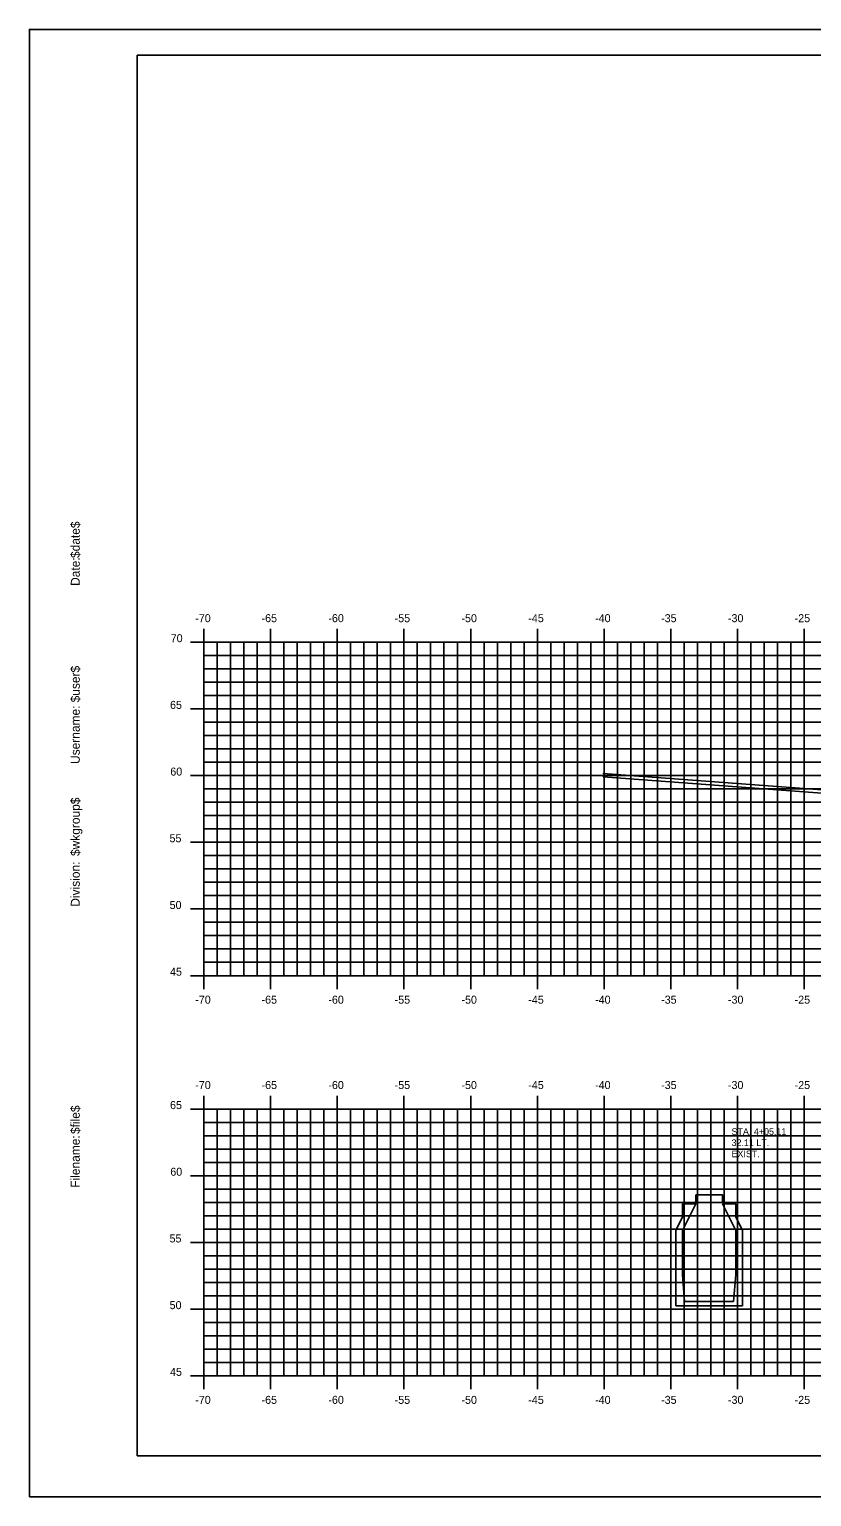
# Model space of a CAD drawing. Extents: x 1026213 to 1026383, y 394615 to 394725.
# Drawn here: x 1026213.3 to 1026272, y 394614.9 to 394724.9 of the extents above; entities that cross this region are included whole.
import ezdxf

# ---------------------------------------------------------------- set-up
doc = ezdxf.new("R2010")
doc.units = 0
for name, color, linetype in [('BORDER', 7, 'Continuous'), ('D_Text_Monospaced', 7, 'Continuous'), ('H_V ANNOTATION', 7, 'Continuous'), ('MAJOR', 7, 'Continuous'), ('MINOR', 7, 'Continuous'), ('PLOT BOUNDARY', 7, 'Continuous'), ('S_Drainage_CB', 7, 'Continuous'), ('S_Roadway_Centerline', 7, 'Continuous')]:
    doc.layers.add(name, color=color, linetype=linetype)

msp = doc.modelspace()

# ---------------------------------------------------------------- linework, layer by layer
at = {"layer": 'BORDER'}
for p, q in [((1026381.43, 394722.93), (1026221.43, 394722.93)), ((1026221.43, 394722.93), (1026221.43, 394617.93)), ((1026221.43, 394617.93), (1026381.43, 394617.93))]:
    msp.add_line(p, q, dxfattribs=at)
at = {"layer": 'MAJOR'}
for p, q in [((1026225.43, 394678.93), (1026226.43, 394678.93)), ((1026226.43, 394679.93), (1026226.43, 394678.93)), ((1026226.43, 394678.93), (1026366.43, 394678.93)), ((1026226.43, 394653.93), (1026226.43, 394678.93)), ((1026231.43, 394679.93), (1026231.43, 394678.93)), ((1026231.43, 394653.93), (1026231.43, 394678.93)), ((1026236.43, 394679.93), (1026236.43, 394678.93)), ((1026236.43, 394653.93), (1026236.43, 394678.93)), ((1026241.43, 394679.93), (1026241.43, 394678.93)), ((1026241.43, 394653.93), (1026241.43, 394678.93)), ((1026246.43, 394679.93), (1026246.43, 394678.93)), ((1026246.43, 394653.93), (1026246.43, 394678.93)), ((1026251.43, 394679.93), (1026251.43, 394678.93)), ((1026251.43, 394653.93), (1026251.43, 394678.93)), ((1026256.43, 394679.93), (1026256.43, 394678.93)), ((1026256.43, 394653.93), (1026256.43, 394678.93)), ((1026261.43, 394679.93), (1026261.43, 394678.93)), ((1026261.43, 394653.93), (1026261.43, 394678.93)), ((1026266.43, 394679.93), (1026266.43, 394678.93)), ((1026266.43, 394653.93), (1026266.43, 394678.93)), ((1026271.43, 394679.93), (1026271.43, 394678.93)), ((1026271.43, 394653.93), (1026271.43, 394678.93)), ((1026225.43, 394673.93), (1026226.43, 394673.93)), ((1026226.43, 394673.93), (1026366.43, 394673.93)), ((1026225.43, 394668.93), (1026226.43, 394668.93)), ((1026226.43, 394668.93), (1026366.43, 394668.93)), ((1026225.43, 394663.93), (1026226.43, 394663.93)), ((1026226.43, 394663.93), (1026366.43, 394663.93)), ((1026225.43, 394658.93), (1026226.43, 394658.93)), ((1026226.43, 394658.93), (1026366.43, 394658.93)), ((1026225.43, 394653.93), (1026226.43, 394653.93)), ((1026226.43, 394653.93), (1026366.43, 394653.93)), ((1026226.43, 394652.93), (1026226.43, 394653.93)), ((1026231.43, 394652.93), (1026231.43, 394653.93)), ((1026236.43, 394652.93), (1026236.43, 394653.93)), ((1026241.43, 394652.93), (1026241.43, 394653.93)), ((1026246.43, 394652.93), (1026246.43, 394653.93)), ((1026251.43, 394652.93), (1026251.43, 394653.93)), ((1026256.43, 394652.93), (1026256.43, 394653.93)), ((1026261.43, 394652.93), (1026261.43, 394653.93)), ((1026266.43, 394652.93), (1026266.43, 394653.93)), ((1026271.43, 394652.93), (1026271.43, 394653.93)), ((1026226.43, 394644.93), (1026226.43, 394643.93)), ((1026231.43, 394644.93), (1026231.43, 394643.93)), ((1026236.43, 394644.93), (1026236.43, 394643.93)), ((1026241.43, 394644.93), (1026241.43, 394643.93)), ((1026246.43, 394644.93), (1026246.43, 394643.93)), ((1026251.43, 394644.93), (1026251.43, 394643.93)), ((1026256.43, 394644.93), (1026256.43, 394643.93)), ((1026261.43, 394644.93), (1026261.43, 394643.93)), ((1026266.43, 394644.93), (1026266.43, 394643.93)), ((1026271.43, 394644.93), (1026271.43, 394643.93)), ((1026225.43, 394643.93), (1026226.43, 394643.93)), ((1026226.43, 394643.93), (1026366.43, 394643.93)), ((1026226.43, 394623.93), (1026226.43, 394643.93)), ((1026231.43, 394623.93), (1026231.43, 394643.93)), ((1026236.43, 394623.93), (1026236.43, 394643.93)), ((1026241.43, 394623.93), (1026241.43, 394643.93)), ((1026246.43, 394623.93), (1026246.43, 394643.93)), ((1026251.43, 394623.93), (1026251.43, 394643.93)), ((1026256.43, 394623.93), (1026256.43, 394643.93)), ((1026261.43, 394623.93), (1026261.43, 394643.93)), ((1026266.43, 394623.93), (1026266.43, 394643.93)), ((1026271.43, 394623.93), (1026271.43, 394643.93)), ((1026225.43, 394638.93), (1026226.43, 394638.93)), ((1026226.43, 394638.93), (1026366.43, 394638.93)), ((1026225.43, 394633.93), (1026226.43, 394633.93)), ((1026226.43, 394633.93), (1026366.43, 394633.93)), ((1026225.43, 394628.93), (1026226.43, 394628.93)), ((1026226.43, 394628.93), (1026366.43, 394628.93)), ((1026225.43, 394623.93), (1026226.43, 394623.93)), ((1026226.43, 394623.93), (1026366.43, 394623.93)), ((1026226.43, 394622.93), (1026226.43, 394623.93)), ((1026231.43, 394622.93), (1026231.43, 394623.93)), ((1026236.43, 394622.93), (1026236.43, 394623.93)), ((1026241.43, 394622.93), (1026241.43, 394623.93)), ((1026246.43, 394622.93), (1026246.43, 394623.93)), ((1026251.43, 394622.93), (1026251.43, 394623.93)), ((1026256.43, 394622.93), (1026256.43, 394623.93)), ((1026261.43, 394622.93), (1026261.43, 394623.93)), ((1026266.43, 394622.93), (1026266.43, 394623.93)), ((1026271.43, 394622.93), (1026271.43, 394623.93))]:
    msp.add_line(p, q, dxfattribs=at)
at = {"layer": 'MINOR'}
for p, q in [((1026227.43, 394653.93), (1026227.43, 394678.93)), ((1026228.43, 394653.93), (1026228.43, 394678.93)), ((1026229.43, 394653.93), (1026229.43, 394678.93)), ((1026230.43, 394653.93), (1026230.43, 394678.93)), ((1026232.43, 394653.93), (1026232.43, 394678.93)), ((1026233.43, 394653.93), (1026233.43, 394678.93)), ((1026234.43, 394653.93), (1026234.43, 394678.93)), ((1026235.43, 394653.93), (1026235.43, 394678.93)), ((1026237.43, 394653.93), (1026237.43, 394678.93)), ((1026238.43, 394653.93), (1026238.43, 394678.93)), ((1026239.43, 394653.93), (1026239.43, 394678.93)), ((1026240.43, 394653.93), (1026240.43, 394678.93)), ((1026242.43, 394653.93), (1026242.43, 394678.93)), ((1026243.43, 394653.93), (1026243.43, 394678.93)), ((1026244.43, 394653.93), (1026244.43, 394678.93)), ((1026245.43, 394653.93), (1026245.43, 394678.93)), ((1026247.43, 394653.93), (1026247.43, 394678.93)), ((1026248.43, 394653.93), (1026248.43, 394678.93)), ((1026249.43, 394653.93), (1026249.43, 394678.93)), ((1026250.43, 394653.93), (1026250.43, 394678.93)), ((1026252.43, 394653.93), (1026252.43, 394678.93)), ((1026253.43, 394653.93), (1026253.43, 394678.93)), ((1026254.43, 394653.93), (1026254.43, 394678.93)), ((1026255.43, 394653.93), (1026255.43, 394678.93)), ((1026257.43, 394653.93), (1026257.43, 394678.93)), ((1026258.43, 394653.93), (1026258.43, 394678.93)), ((1026259.43, 394653.93), (1026259.43, 394678.93)), ((1026260.43, 394653.93), (1026260.43, 394678.93)), ((1026262.43, 394653.93), (1026262.43, 394678.93)), ((1026263.43, 394653.93), (1026263.43, 394678.93)), ((1026264.43, 394653.93), (1026264.43, 394678.93)), ((1026265.43, 394653.93), (1026265.43, 394678.93)), ((1026267.43, 394653.93), (1026267.43, 394678.93)), ((1026268.43, 394653.93), (1026268.43, 394678.93)), ((1026269.43, 394653.93), (1026269.43, 394678.93)), ((1026270.43, 394653.93), (1026270.43, 394678.93)), ((1026226.43, 394677.93), (1026366.43, 394677.93)), ((1026226.43, 394677.93), (1026227.44, 394677.93)), ((1026226.43, 394676.93), (1026366.43, 394676.93)), ((1026226.43, 394676.93), (1026227.44, 394676.93)), ((1026226.43, 394675.93), (1026366.43, 394675.93)), ((1026226.43, 394675.93), (1026227.44, 394675.93)), ((1026226.43, 394674.93), (1026366.43, 394674.93)), ((1026226.43, 394674.93), (1026227.44, 394674.93)), ((1026226.43, 394672.93), (1026366.43, 394672.93)), ((1026226.43, 394672.93), (1026227.44, 394672.93)), ((1026226.43, 394671.93), (1026366.43, 394671.93)), ((1026226.43, 394671.93), (1026227.44, 394671.93)), ((1026226.43, 394670.93), (1026366.43, 394670.93)), ((1026226.43, 394670.93), (1026227.44, 394670.93)), ((1026226.43, 394669.93), (1026366.43, 394669.93)), ((1026226.43, 394669.93), (1026227.44, 394669.93)), ((1026226.43, 394667.93), (1026366.43, 394667.93)), ((1026226.43, 394667.93), (1026227.44, 394667.93)), ((1026226.43, 394666.93), (1026366.43, 394666.93)), ((1026226.43, 394666.93), (1026227.44, 394666.93)), ((1026226.43, 394665.93), (1026366.43, 394665.93)), ((1026226.43, 394665.93), (1026227.44, 394665.93)), ((1026226.43, 394664.93), (1026366.43, 394664.93)), ((1026226.43, 394664.93), (1026227.44, 394664.93)), ((1026226.43, 394662.93), (1026366.43, 394662.93)), ((1026226.43, 394662.93), (1026227.44, 394662.93)), ((1026226.43, 394661.93), (1026366.43, 394661.93)), ((1026226.43, 394661.93), (1026227.44, 394661.93)), ((1026226.43, 394660.93), (1026366.43, 394660.93)), ((1026226.43, 394660.93), (1026227.44, 394660.93)), ((1026226.43, 394659.93), (1026366.43, 394659.93)), ((1026226.43, 394659.93), (1026227.44, 394659.93)), ((1026226.43, 394657.93), (1026366.43, 394657.93)), ((1026226.43, 394657.93), (1026227.44, 394657.93)), ((1026226.43, 394656.93), (1026366.43, 394656.93)), ((1026226.43, 394656.93), (1026227.44, 394656.93)), ((1026226.43, 394655.93), (1026366.43, 394655.93)), ((1026226.43, 394655.93), (1026227.44, 394655.93)), ((1026226.43, 394654.93), (1026366.43, 394654.93)), ((1026226.43, 394654.93), (1026227.44, 394654.93)), ((1026227.43, 394623.93), (1026227.43, 394643.93)), ((1026228.43, 394623.93), (1026228.43, 394643.93)), ((1026229.43, 394623.93), (1026229.43, 394643.93)), ((1026230.43, 394623.93), (1026230.43, 394643.93)), ((1026232.43, 394623.93), (1026232.43, 394643.93)), ((1026233.43, 394623.93), (1026233.43, 394643.93)), ((1026234.43, 394623.93), (1026234.43, 394643.93)), ((1026235.43, 394623.93), (1026235.43, 394643.93)), ((1026237.43, 394623.93), (1026237.43, 394643.93)), ((1026238.43, 394623.93), (1026238.43, 394643.93)), ((1026239.43, 394623.93), (1026239.43, 394643.93)), ((1026240.43, 394623.93), (1026240.43, 394643.93)), ((1026242.43, 394623.93), (1026242.43, 394643.93)), ((1026243.43, 394623.93), (1026243.43, 394643.93)), ((1026244.43, 394623.93), (1026244.43, 394643.93)), ((1026245.43, 394623.93), (1026245.43, 394643.93)), ((1026247.43, 394623.93), (1026247.43, 394643.93)), ((1026248.43, 394623.93), (1026248.43, 394643.93)), ((1026249.43, 394623.93), (1026249.43, 394643.93)), ((1026250.43, 394623.93), (1026250.43, 394643.93)), ((1026252.43, 394623.93), (1026252.43, 394643.93)), ((1026253.43, 394623.93), (1026253.43, 394643.93)), ((1026254.43, 394623.93), (1026254.43, 394643.93)), ((1026255.43, 394623.93), (1026255.43, 394643.93)), ((1026257.43, 394623.93), (1026257.43, 394643.93)), ((1026258.43, 394623.93), (1026258.43, 394643.93)), ((1026259.43, 394623.93), (1026259.43, 394643.93)), ((1026260.43, 394623.93), (1026260.43, 394643.93)), ((1026262.43, 394623.93), (1026262.43, 394643.93)), ((1026263.43, 394623.93), (1026263.43, 394643.93)), ((1026264.43, 394623.93), (1026264.43, 394643.93)), ((1026265.43, 394623.93), (1026265.43, 394643.93)), ((1026267.43, 394623.93), (1026267.43, 394643.93)), ((1026268.43, 394623.93), (1026268.43, 394643.93)), ((1026269.43, 394623.93), (1026269.43, 394643.93)), ((1026270.43, 394623.93), (1026270.43, 394643.93)), ((1026226.43, 394642.93), (1026366.43, 394642.93)), ((1026226.43, 394642.93), (1026227.44, 394642.93)), ((1026226.43, 394641.93), (1026366.43, 394641.93)), ((1026226.43, 394641.93), (1026227.44, 394641.93)), ((1026226.43, 394640.93), (1026366.43, 394640.93)), ((1026226.43, 394640.93), (1026227.44, 394640.93)), ((1026226.43, 394639.93), (1026366.43, 394639.93)), ((1026226.43, 394639.93), (1026227.44, 394639.93)), ((1026226.43, 394637.93), (1026366.43, 394637.93)), ((1026226.43, 394637.93), (1026227.44, 394637.93)), ((1026226.43, 394636.93), (1026366.43, 394636.93)), ((1026226.43, 394636.93), (1026227.44, 394636.93)), ((1026226.43, 394635.93), (1026366.43, 394635.93)), ((1026226.43, 394635.93), (1026227.44, 394635.93)), ((1026226.43, 394634.93), (1026366.43, 394634.93)), ((1026226.43, 394634.93), (1026227.44, 394634.93)), ((1026226.43, 394632.93), (1026366.43, 394632.93)), ((1026226.43, 394632.93), (1026227.44, 394632.93)), ((1026226.43, 394631.93), (1026366.43, 394631.93)), ((1026226.43, 394631.93), (1026227.44, 394631.93)), ((1026226.43, 394630.93), (1026366.43, 394630.93)), ((1026226.43, 394630.93), (1026227.44, 394630.93)), ((1026226.43, 394629.93), (1026366.43, 394629.93)), ((1026226.43, 394629.93), (1026227.44, 394629.93)), ((1026226.43, 394627.93), (1026366.43, 394627.93)), ((1026226.43, 394627.93), (1026227.44, 394627.93)), ((1026226.43, 394626.93), (1026366.43, 394626.93)), ((1026226.43, 394626.93), (1026227.44, 394626.93)), ((1026226.43, 394625.93), (1026366.43, 394625.93)), ((1026226.43, 394625.93), (1026227.44, 394625.93)), ((1026226.43, 394624.93), (1026366.43, 394624.93)), ((1026226.43, 394624.93), (1026227.44, 394624.93))]:
    msp.add_line(p, q, dxfattribs=at)
at = {"layer": 'PLOT BOUNDARY'}
msp.add_lwpolyline([(1026213.34, 394614.87), (1026383.34, 394614.87), (1026383.34, 394724.87), (1026213.34, 394724.87)], close=True, dxfattribs=at)
at = {"layer": 'S_Drainage_CB'}
for p, q in [((1026262.31, 394635.84), (1026262.31, 394636.83)), ((1026262.31, 394636.83), (1026263.32, 394636.83)), ((1026263.32, 394636.83), (1026262.31, 394634.83)), ((1026262.31, 394635.84), (1026262.31, 394636.83)), ((1026262.31, 394636.83), (1026263.32, 394636.83)), ((1026263.32, 394636.83), (1026262.31, 394634.83)), ((1026265.32, 394636.83), (1026266.31, 394636.83)), ((1026266.31, 394634.83), (1026265.32, 394636.83)), ((1026265.32, 394636.83), (1026266.31, 394636.83)), ((1026266.31, 394634.83), (1026265.32, 394636.83)), ((1026266.31, 394636.83), (1026266.31, 394635.84)), ((1026266.31, 394636.83), (1026266.31, 394635.84)), ((1026261.81, 394634.83), (1026262.31, 394635.84)), ((1026261.81, 394634.83), (1026262.31, 394635.84)), ((1026266.31, 394635.84), (1026266.8, 394634.83)), ((1026266.31, 394635.84), (1026266.8, 394634.83)), ((1026261.81, 394629.18), (1026261.81, 394634.83)), ((1026261.81, 394629.18), (1026261.81, 394634.83)), ((1026262.31, 394634.83), (1026262.31, 394631.51)), ((1026262.31, 394634.83), (1026262.31, 394631.51)), ((1026266.31, 394631.51), (1026266.31, 394634.83)), ((1026266.31, 394631.51), (1026266.31, 394634.83)), ((1026266.8, 394634.83), (1026266.8, 394629.18)), ((1026266.8, 394634.83), (1026266.8, 394629.18)), ((1026262.31, 394631.51), (1026262.47, 394629.51)), ((1026262.31, 394631.51), (1026262.47, 394629.51)), ((1026266.14, 394629.51), (1026266.31, 394631.51)), ((1026266.14, 394629.51), (1026266.31, 394631.51)), ((1026262.47, 394629.51), (1026266.14, 394629.51)), ((1026262.47, 394629.51), (1026266.14, 394629.51)), ((1026266.8, 394629.18), (1026261.81, 394629.18)), ((1026266.8, 394629.18), (1026261.81, 394629.18))]:
    msp.add_line(p, q, dxfattribs=at)
msp.add_lwpolyline([(1026262.83, 394636.87), (1026263.32, 394636.87), (1026263.32, 394637.49), (1026265.32, 394637.49), (1026265.32, 394636.87), (1026265.82, 394636.87)], dxfattribs=at)
msp.add_lwpolyline([(1026262.83, 394636.87), (1026263.32, 394636.87), (1026263.32, 394637.49), (1026265.32, 394637.49), (1026265.32, 394636.87), (1026265.82, 394636.87)], dxfattribs=at)
at = {"layer": 'S_Roadway_Centerline'}
for points in [[(1026256.36, 394669.08), (1026256.36, 394669.08), (1026258.36, 394668.94), (1026278.77, 394667.41), (1026280.04, 394667.3), (1026280.16, 394667.29), (1026299.85, 394666.05), (1026302.39, 394665.94), (1026303.98, 394665.86), (1026303.98, 394665.86), (1026303.98, 394665.86), (1026309.14, 394665.64), (1026309.14, 394665.64), (1026312.05, 394665.32), (1026323.69, 394664.41), (1026333.54, 394663.54), (1026333.54, 394663.54), (1026333.55, 394663.54), (1026346.49, 394662.46), (1026346.49, 394662.46), (1026363.44, 394661.04), (1026365.47, 394660.9), (1026365.47, 394660.9), (1026366.43, 394660.82)], [(1026256.36, 394668.83), (1026256.36, 394668.83), (1026258.36, 394668.69), (1026278.77, 394667.16), (1026280.04, 394667.05), (1026280.16, 394667.04), (1026299.85, 394665.8), (1026302.39, 394665.69), (1026303.98, 394665.61), (1026303.98, 394665.61), (1026303.98, 394665.61), (1026309.14, 394665.39), (1026309.14, 394665.39), (1026312.05, 394665.07), (1026323.69, 394664.16), (1026333.54, 394663.29), (1026333.54, 394663.29), (1026333.55, 394663.29), (1026346.49, 394662.21), (1026346.49, 394662.21), (1026363.44, 394660.79), (1026365.47, 394660.65), (1026365.47, 394660.65), (1026366.43, 394660.57)]]:
    msp.add_lwpolyline(points, dxfattribs=at)

# ---------------------------------------------------------------- texts
at = {"layer": 'BORDER'}
for s, p in [('$date$', (1026217.12, 394685.24)), ('Date:', (1026217.12, 394683.15)), ('$user$', (1026217.12, 394674.42)), ('Username:', (1026217.12, 394669.8)), ('$wkgroup$', (1026217.12, 394662.9)), ('Division:', (1026217.12, 394659.1)), ('$file$', (1026217.12, 394642.06)), ('Filename:', (1026217.12, 394638.03))]:
    msp.add_text(s, height=0.67, rotation=90, dxfattribs=at).set_placement(p)
at = {"layer": 'D_Text_Monospaced'}
for s, p in [('STA. 4+05.11', (1026265.99, 394641.99)), ('STA. 4+05.11', (1026265.99, 394641.99)), ('32.11 LT.', (1026265.99, 394641.16)), ('32.11 LT.', (1026265.99, 394641.16)), ('EXIST. ', (1026265.99, 394640.32)), ('EXIST. ', (1026265.99, 394640.32))]:
    msp.add_text(s, height=0.5, dxfattribs=at).set_placement(p)
at = {"layer": 'H_V ANNOTATION'}
for s, p in [('-70', (1026225.78, 394680.43)), ('-65', (1026230.75, 394680.43)), ('-60', (1026235.76, 394680.43)), ('-55', (1026240.73, 394680.43)), ('-50', (1026245.74, 394680.43)), ('-45', (1026250.75, 394680.43)), ('-40', (1026255.76, 394680.43)), ('-35', (1026260.71, 394680.43)), ('-30', (1026265.72, 394680.43)), ('-25', (1026270.72, 394680.43)), ('70', (1026223.94, 394678.93)), ('65', (1026223.89, 394673.93)), ('60', (1026223.91, 394668.93)), ('55', (1026223.85, 394663.93)), ('50', (1026223.86, 394658.93)), ('45', (1026223.89, 394653.93)), ('-70', (1026225.78, 394651.83)), ('-65', (1026230.75, 394651.83)), ('-60', (1026235.76, 394651.83)), ('-55', (1026240.73, 394651.83)), ('-50', (1026245.74, 394651.83)), ('-45', (1026250.75, 394651.83)), ('-40', (1026255.76, 394651.83)), ('-35', (1026260.71, 394651.83)), ('-30', (1026265.72, 394651.83)), ('-25', (1026270.72, 394651.83)), ('-70', (1026225.78, 394645.43)), ('-65', (1026230.75, 394645.43)), ('-60', (1026235.76, 394645.43)), ('-55', (1026240.73, 394645.43)), ('-50', (1026245.74, 394645.43)), ('-45', (1026250.75, 394645.43)), ('-40', (1026255.76, 394645.43)), ('-35', (1026260.71, 394645.43)), ('-30', (1026265.72, 394645.43)), ('-25', (1026270.72, 394645.43)), ('65', (1026223.89, 394643.93)), ('60', (1026223.91, 394638.93)), ('55', (1026223.85, 394633.93)), ('50', (1026223.86, 394628.93)), ('45', (1026223.89, 394623.93)), ('-70', (1026225.78, 394621.83)), ('-65', (1026230.75, 394621.83)), ('-60', (1026235.76, 394621.83)), ('-55', (1026240.73, 394621.83)), ('-50', (1026245.74, 394621.83)), ('-45', (1026250.75, 394621.83)), ('-40', (1026255.76, 394621.83)), ('-35', (1026260.71, 394621.83)), ('-30', (1026265.72, 394621.83)), ('-25', (1026270.72, 394621.83))]:
    msp.add_text(s, height=0.6, dxfattribs=at).set_placement(p)

doc.saveas('drawing.dxf')
